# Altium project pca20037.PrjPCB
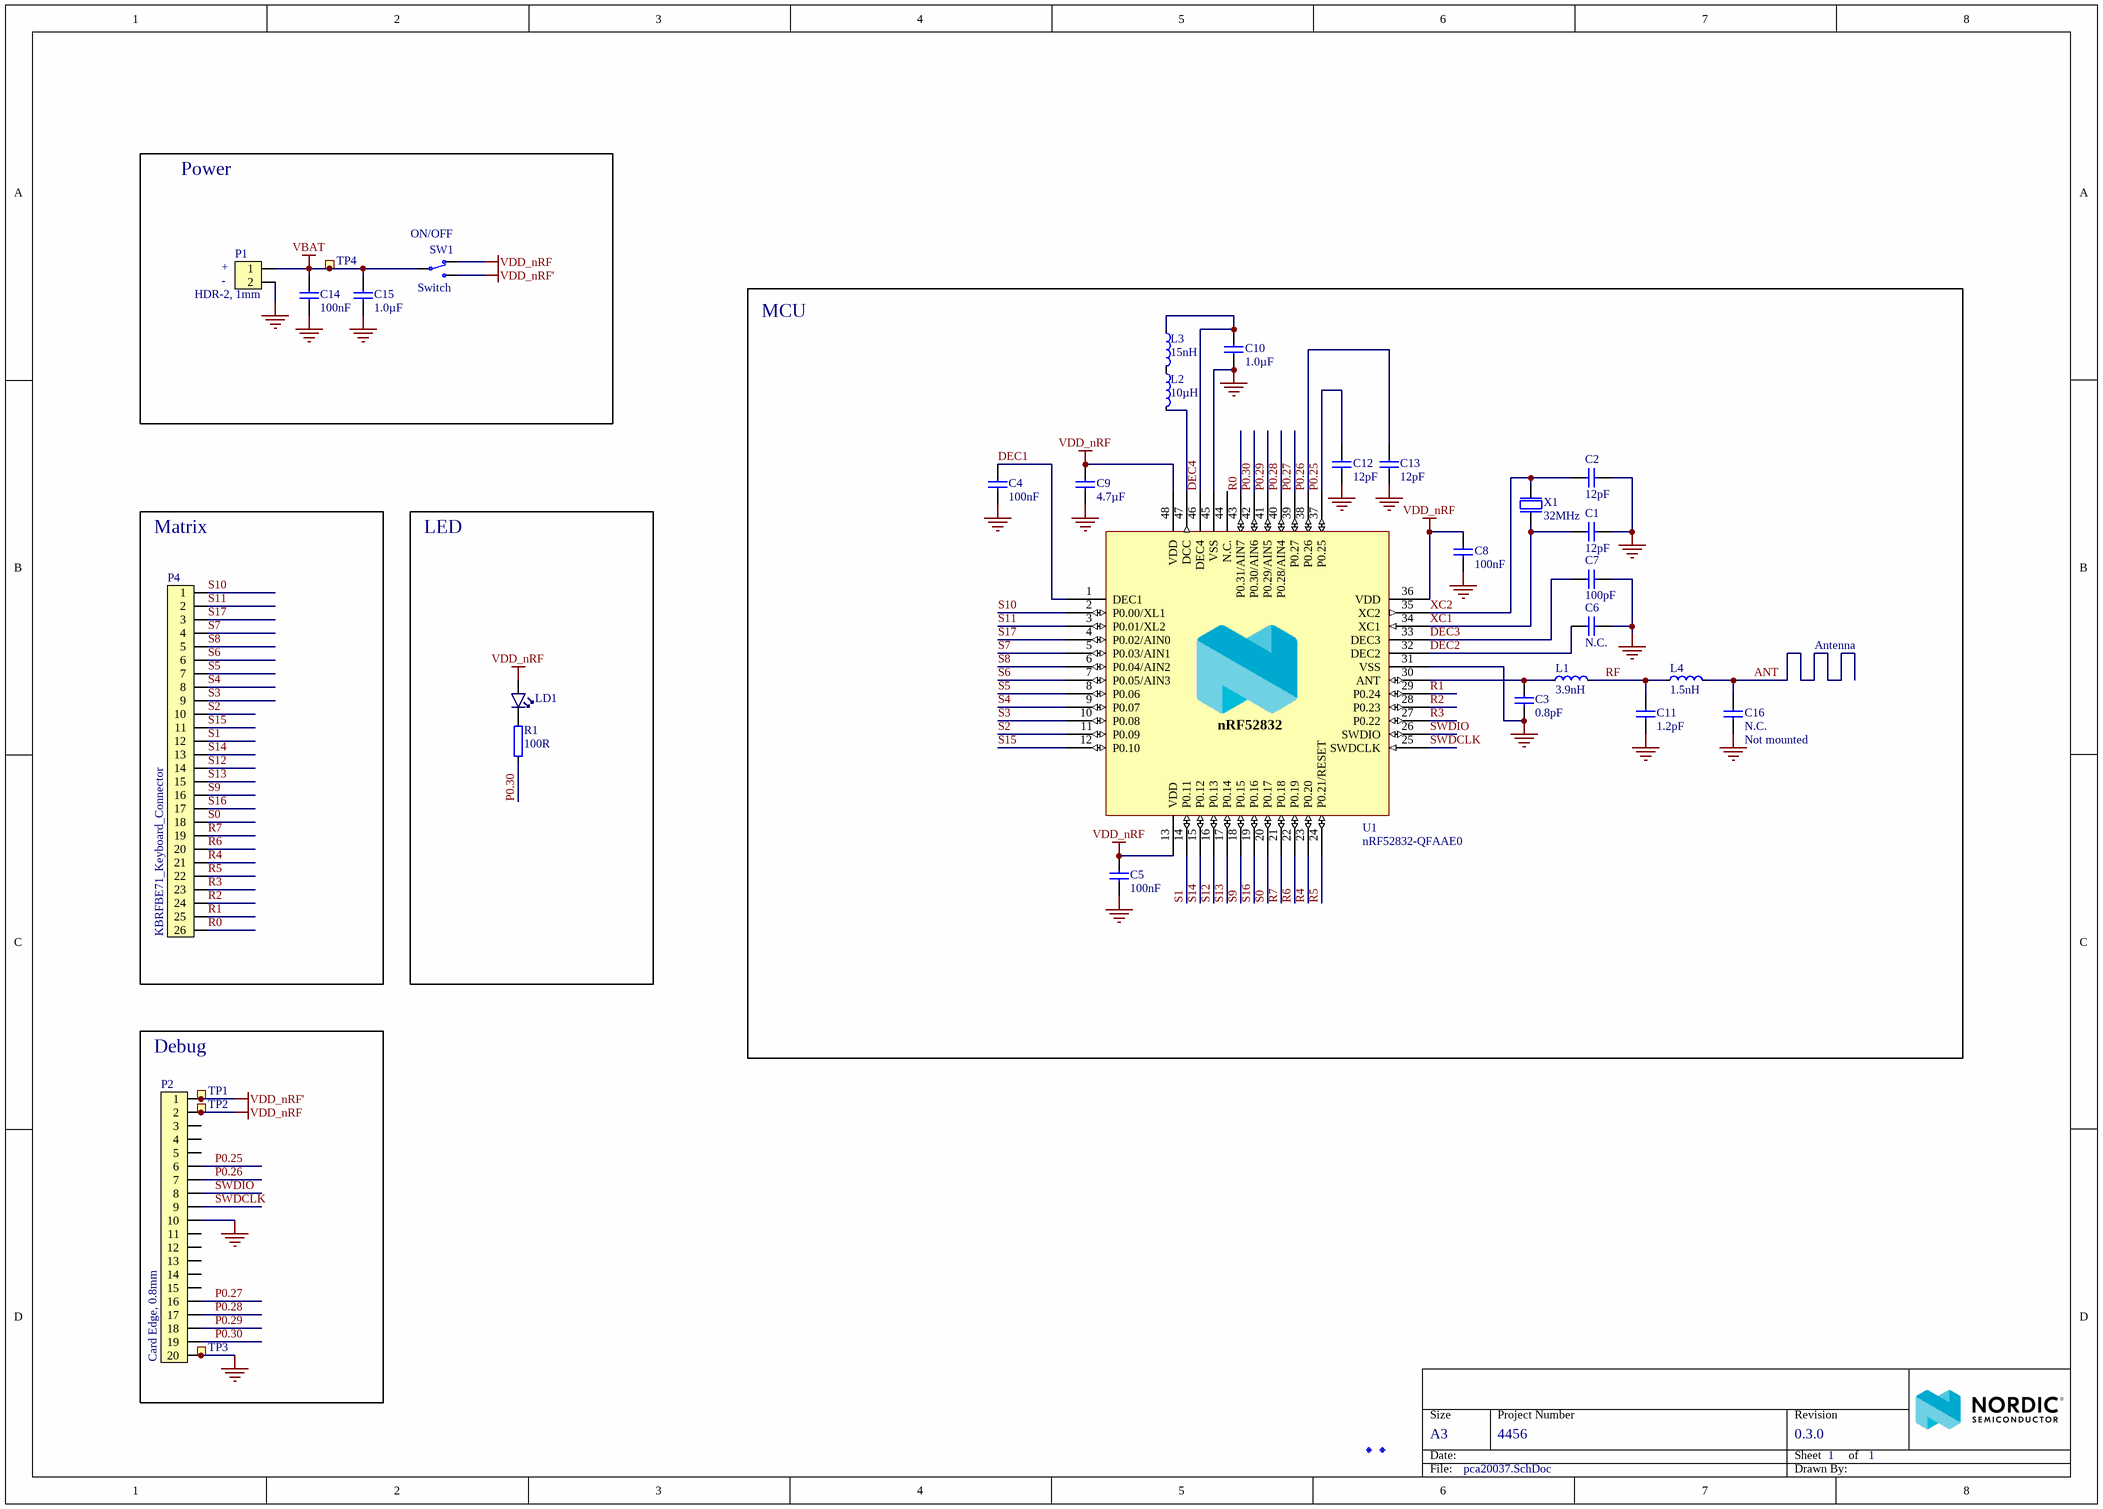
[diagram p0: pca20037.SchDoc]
Author: KJP/MASI; BoardThickness: 1.2mm; BoardTitle: nRF52832 Desktop Keyboard; NrOfLayers: 2; Organization: Nordic Semiconductor; PCAName: PCA20037; PCBNumber: 400342; PCBRevision: 0015MASI; PCBStackup: 2001; ProjectName: Demo Projects Applications Group; ProjectNumber: 4456; Revision: 0.3.0; SilkscreenColor: White; SoldermaskColor: Blue; SurfaceFinish: Lead-Free HASL
1 sheet, 34 parts. Net scope: global (net labels, ports and power ports of the same name join across sheets).
Board file: 400342.PcbDoc

## Sheet pca20037.SchDoc: =BoardTitle
size A3; Organization: Nordic Semiconductor; DocumentNumber: 1; Revision: 0.3.0; SheetNumber: 1; SheetTotal: 1; Author: KJP/MASI; CompanyName: Nordic Semiconductor; DrawnBy: KJP/MASI; ProjectNumber: 4456

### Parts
C1  12pF  [CAPC1005X04L]
C2  12pF  [CAPC1005X04L]
C3  0.8pF  [CAPC1005X04L]
C4  100nF  [CAPC1005X04L]
C5  100nF  [CAPC1005X04L]
C6  N.C.  [CAPC1005X04L]
C7  100pF  [CAPC1005X04L]
C8  100nF  [CAPC1005X04L]
C9  4.7µF  [CAPC1608X06L]
C10  1.0µF  [CAPC1608X06L]
C11  1.2pF  [CAPC1005X04L]
C12  12pF  [CAPC1005X04L]
C13  12pF  [CAPC1005X04L]
C14  100nF  [CAPC1005X04L]
C15  1.0µF  [CAPC1608X06L]
C16  N.C.  Assembly: Not mounted  [CAPC1005X04L]
Fiducual1  Fiducial mark  [Fiducial]  (value not drawn)
Fiducual2  Fiducial mark  [Fiducial]  (value not drawn)
L1  3.9nH  [INDC1005X04L]
L2  10µH  [INDC1608X06L]
L3  15nH  [INDC1005X04L]
L4  1.5nH  [INDC1005X04L]
LD1  L0603R  [LED_0603_R]  (value not drawn)
P1  HDR-2, 1mm  [SM02B-SRSS-TB]
P2  Card Edge, 0.8mm  [10056847-101LF]
P4  KBRFBE71_Keyboard_Connector  [KBRFBE71_Keyboard_Connector]
R1  100R  [RESC1005X04L]
SW1  Switch  [JS102011SAQN]
TP1  Ø0.7mm,SMD  [TP_SMD_Ø0.7mm]  (value not drawn)  (no BOM)
TP2  Ø0.7mm,SMD  [TP_SMD_Ø0.7mm]  (value not drawn)  (no BOM)
TP3  Ø0.7mm,SMD  [TP_SMD_Ø0.7mm]  (value not drawn)  (no BOM)
TP4  Ø0.7mm,SMD  [TP_SMD_Ø0.7mm]  (value not drawn)  (no BOM)
U1  nRF52832-QFAAE0  [QFN40P600X600X90-48N]
X1  32MHz  [BT-XTAL_2016]

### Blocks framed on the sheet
Power: C14 C15 P1 SW1 TP4
MCU: C1-C13 C16 L1-L4 U1 X1
Matrix: P4
LED: LD1 R1
Debug: P2 TP1-TP3

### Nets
GND: C1.2 C2.2 C3.1 C4.2 C5.2 C6.1 C7.2 C8.2 C9.2 C10.1 C11.2 C12.2 C13.2 C14.1 C15.1 C16.1 P1.2 P2.10 P2.20 TP3.1 U1.31(VSS) U1.45(VSS) U1.49(GND) X1.2(GND) X1.4(GND)
VBAT: C14.2 C15.2 P1.1 SW1.2(COM) TP4.1
VDD_nRF: C5.1 C8.1 C9.1 LD1.2(A) P2.2 SW1.1(N.C) TP2.1 U1.13(VDD) U1.36(VDD) U1.48(VDD)
VDD_nRF': P2.1 SW1.3(N.O) TP1.1
ANT: C16.2 L4.2
DEC1: C4.1 U1.1(DEC1)
DEC2: C6.2 U1.32(DEC2)
DEC3: C7.1 U1.33(DEC3)
DEC4: C10.2 L3.1 U1.46(DEC4)
P0.25: C12.1 P2.6 U1.37(P0.25)
P0.26: C13.1 P2.7 U1.38(P0.26)
P0.27: P2.16 U1.39(P0.27)
P0.28: P2.17 U1.40(P0.28/AIN4)
P0.29: P2.18 U1.41(P0.29/AIN5)
P0.30: P2.19 R1.1 U1.42(P0.30/AIN6)
R0: P4.26 U1.43(P0.31/AIN7)
R1: P4.25 U1.29(P0.24)
R2: P4.24 U1.28(P0.23)
R3: P4.23 U1.27(P0.22)
R4: P4.21 U1.23(P0.20)
R5: P4.22 U1.24(P0.21/RESET)
R6: P4.20 U1.22(P0.19)
R7: P4.19 U1.21(P0.18)
RF: C11.1 L1.2 L4.1
S0: P4.18 U1.20(P0.17)
S1: P4.12 U1.14(P0.11)
S2: P4.10 U1.11(P0.09)
S3: P4.9 U1.10(P0.08)
S4: P4.8 U1.9(P0.07)
S5: P4.7 U1.8(P0.06)
S6: P4.6 U1.7(P0.05/AIN3)
S7: P4.4 U1.5(P0.03/AIN1)
S8: P4.5 U1.6(P0.04/AIN2)
S9: P4.16 U1.18(P0.15)
S10: P4.1 U1.2(P0.00/XL1)
S11: P4.2 U1.3(P0.01/XL2)
S12: P4.14 U1.16(P0.13)
S13: P4.15 U1.17(P0.14)
S14: P4.13 U1.15(P0.12)
S15: P4.11 U1.12(P0.10)
S16: P4.17 U1.19(P0.16)
S17: P4.3 U1.4(P0.02/AIN0)
SWDCLK: P2.9 U1.25(SWDCLK)
SWDIO: P2.8 U1.26(SWDIO)
XC1: C1.1 U1.34(XC1) X1.1(inp)
XC2: C2.1 U1.35(XC2) X1.3(out)
NetC3_2: C3.2 L1.1 U1.30(ANT)
NetL2_1: L2.1 L3.2
NetL2_2: L2.2 U1.47(DCC)
NetLD1_1: LD1.1(C) R1.2

Not connected (* = marked no-connect by the designer): P2 3 4 5 11 12 13 14 15; U1 44(N.C.)

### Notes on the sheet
- (near SW1) ON/OFF
- (near P1) +
- (near P1) -
- Antenna

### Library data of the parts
C1 C2 C12 C13 = C0402-12p: Capacitor, NP0, ±2%; Part number IPS: 00000002398; Note: 50V; Artikkelnr Noca: 20029159
C3 = C0402-0.8p: Capacitor, NP0, ±5%; Part number IPS: 00000007782; Note: 50V; Artikkelnr Noca: 20029147
C4 C5 C8 C14 = C0402-100n: Capacitor, X7R, ±10%; Part number IPS: 00000005296; Note: 16V; Artikkelnr Noca: 20039200
C6 = C0402-N.C.: Not mounted; Note: Chip Cap; Artikkelnr Noca: N.A.; Assembly: Not mounted
C7 = C0402-100p: Capacitor, NP0, ±5%; Part number IPS: 00000002361; Note: 50V; Artikkelnr Noca: 20029135
C9 = C0603-4µ7: Capacitor, X5R, ±10%; Part number IPS: 00000007783; Note: 6.3V; Artikkelnr Noca: 20069060
C10 C15 = C0603-1µ0: Capacitor, X7R, ±10%; Part number IPS: 00000000616; Note: 16V; Artikkelnr Noca: 20039282
C11 = C0402-1.2p: Capacitor, NP0, ±0.1pF; Part number IPS: 00000005410; Note: 50V; Artikkelnr Noca: 20029157
C16 = C0402-N.C.: Not mounted; Note: Chip Cap; Artikkelnr Noca: N.A.
Fiducual1 Fiducual2 = Fid-Mark: Artikkelnr Noca: N.A.
L1 = L0402-3n9: Inductor, 170mA, ±0.1nH; Manufacturer: Murata; Manufacturer Part Number: LQP15MN3N9B02D; Part number IPS: 00000007793; Note: High frequency chip inductor ±5%; Artikkelnr Noca: 33029151
L2 = L0603-10µ: Inductor, 80mA, ±10%; Manufacturer: Taiyo Yuden; Manufacturer Part Number: LBMF1608T100K; Part number IPS: 00000007794; Note: LBMF1608T100K 10µH 80mA 0603; Artikkelnr Noca: 33029314
L3 = L0402-15n: Inductor, 320mA, ±5%; Manufacturer: Taiyo Yuden; Manufacturer Part Number: HK100515NJ-T; Part number IPS: 00000001262; Note: High frequency chip inductor ±10%; Artikkelnr Noca: 33029323
L4 = L0402-1n5: Inductor, 280mA, ±0.1nH; Manufacturer: Murata; Manufacturer Part Number: LQP15MN1N5B02D; Note: High frequency chip inductor ±5%; Artikkelnr Noca: N.A.
LD1 = EL19-21SURC: LED 0603, EL19-21SURC; Manufacturer: Everlight; Manufacturer Part Number: EL-19-21SURC/S530-A2/TR8; Part number IPS: N.A.; Note: 39 mcd @ 20 mA; Artikkelnr Noca: 13019043
P1 = SM02B-SRSS-TB: 1.0mm pitch connector side entry SMD; Manufacturer: JST; Manufacturer Part Number: SM02B-SRSS-TB(LF)(SN); Part number IPS: 00000007791; Note: JST, Header; Artikkelnr Noca: 55010030
P2 = 10056847-101LF: 0.8mm pitch, dual edge, right angle, SMD, card edge connector; Manufacturer: FCI; Artikkelnr Noca: N.A.
P4 = KBRFBE71_Keyboard_Connector: KBRFBE71 Keyboard Connector; Artikkelnr Noca: N.A.
R1 = R0402-100: Resistor, ±1%, 0.063W; Part number IPS: 00000002811; Note: Chip Res 1%; Artikkelnr Noca: 27049049
SW1 = JS102011SAQN: SMD slide Switch (ON-ON); Manufacturer: C&K Components; Part number IPS: N.A.; Artikkelnr Noca: 50019064
TP1-TP4 = TP_SMD_Ø0.7MM: 0.7mm circular SMD testpad; Manufacturer: Nordic Semiconductor; Artikkelnr Noca: N.A.
U1 = nRF52832-QFAAE0: Multi-protocol Bluetooth Low Energy, ANT and 2.4GHz proprietary system-on-chip; Manufacturer: Nordic Semiconductor; Artikkelnr Noca: N.A.
X1 = XTAL_SMD2016_32MHz_8pF_KDS: XTAL SMD 2016, 32MHz, Cl=8pF, Tol: ±10ppm, Stab: ±20ppm; Manufacturer: KDS; Manufacturer Part Number: DSX211G; Note: XTAL SMD 32.000MHz; Artikkelnr Noca: N.A.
